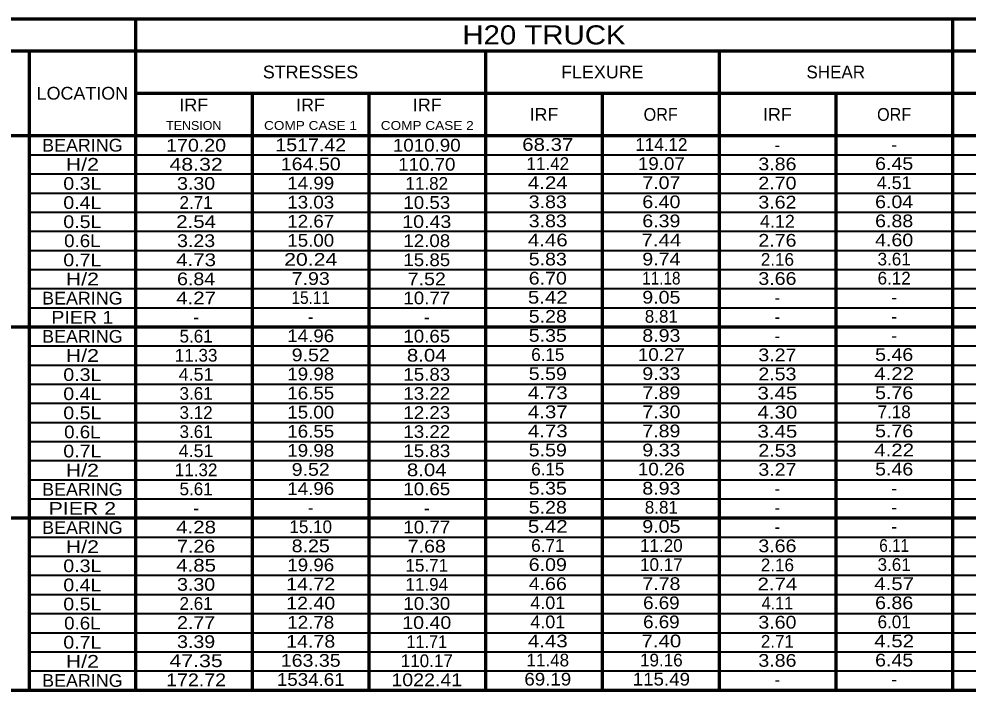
# Model space of a CAD drawing. Extents: x -1807 to -1668, y -81 to 6.
# Drawn here: x -1758.28 to -1713.57, y -25.85 to 5.78 of the extents above; entities that cross this region are included whole.
import ezdxf
from ezdxf.enums import TextEntityAlignment as Align

# ---------------------------------------------------------------- set-up
doc = ezdxf.new("R2010")
doc.units = 0
doc.header["$LTSCALE"] = 0.24
doc.layers.add('1', color=7, linetype='Continuous', lineweight=70)
doc.layers.add('5', color=7, linetype='Continuous', lineweight=40)
doc.layers.add('21', color=7, linetype='Continuous')
doc.layers.add('9', color=7, linetype='Continuous')

msp = doc.modelspace()

# ---------------------------------------------------------------- linework, layer by layer
at = {"layer": '1'}
for p, q in [((-1761.797, 5.7798), (-1675.797, 5.7798)), ((-1752.797, 5.7798), (-1752.797, -25.8503)), ((-1714.297, 5.7798), (-1714.297, -25.8503)), ((-1761.797, 4.2798), (-1675.797, 4.2798)), ((-1757.797, 4.2798), (-1757.797, -25.8503)), ((-1736.297, 4.2798), (-1736.297, -25.8503)), ((-1725.297, 4.2798), (-1725.297, -25.8503)), ((-1752.797, 2.2798), (-1675.797, 2.2798)), ((-1747.297, 2.2798), (-1747.297, -25.8503)), ((-1741.797, 2.2798), (-1741.797, -25.8503)), ((-1730.797, 2.2798), (-1730.797, -25.8503)), ((-1719.797, 2.2798), (-1719.797, -25.8503)), ((-1761.797, 0.2798), (-1675.797, 0.2798)), ((-1761.797, -8.7306), (-1675.797, -8.7306)), ((-1761.797, -17.741), (-1675.797, -17.741)), ((-1761.797, -25.8503), (-1675.797, -25.8503))]:
    msp.add_line(p, q, dxfattribs=at)
at = {"layer": '5'}
for p, q in [((-1757.797, -0.6212), (-1675.797, -0.6212)), ((-1757.797, -1.5222), (-1675.797, -1.5222)), ((-1757.797, -2.4232), (-1675.797, -2.4232)), ((-1757.797, -3.3243), (-1675.797, -3.3243)), ((-1757.797, -4.2253), (-1675.797, -4.2253)), ((-1757.797, -5.1264), (-1675.797, -5.1264)), ((-1757.797, -6.0274), (-1675.797, -6.0274)), ((-1757.797, -6.9285), (-1675.797, -6.9285)), ((-1757.797, -7.8295), (-1675.797, -7.8295)), ((-1757.797, -9.6316), (-1675.797, -9.6316)), ((-1757.797, -10.5327), (-1675.797, -10.5327)), ((-1757.797, -11.4337), (-1675.797, -11.4337)), ((-1757.797, -12.3347), (-1675.797, -12.3347)), ((-1757.797, -13.2357), (-1675.797, -13.2357)), ((-1757.797, -14.1368), (-1675.797, -14.1368)), ((-1757.797, -15.0378), (-1675.797, -15.0378)), ((-1757.797, -15.9389), (-1675.797, -15.9389)), ((-1757.797, -16.8399), (-1675.797, -16.8399)), ((-1757.797, -18.642), (-1675.797, -18.642)), ((-1757.797, -19.5431), (-1675.797, -19.5431)), ((-1757.797, -20.4441), (-1675.797, -20.4441)), ((-1757.797, -21.3452), (-1675.797, -21.3452)), ((-1757.797, -22.2462), (-1675.797, -22.2462)), ((-1757.797, -23.1472), (-1675.797, -23.1472)), ((-1757.797, -24.0482), (-1675.797, -24.0482)), ((-1757.797, -24.9493), (-1675.797, -24.9493))]:
    msp.add_line(p, q, dxfattribs=at)

# ---------------------------------------------------------------- texts
at = {"layer": '1'}
for s, width, p in [('BEARING', 1.05, (-1755.2967, -0.4707)), ('H/2', 1.25, (-1755.2969, -1.3717)), ('0.3L', 1.15, (-1755.2968, -2.2727)), ('0.4L', 1.15, (-1755.2968, -3.1738)), ('0.5L', 1.15, (-1755.2968, -4.0748)), ('0.6L', 1.1, (-1755.2969, -4.9758)), ('0.7L', 1.15, (-1755.2968, -5.8769)), ('H/2', 1.25, (-1755.2969, -6.7779)), ('BEARING', 1.05, (-1755.2967, -7.679)), ('PIER 1', 1.15, (-1755.2968, -8.58)), ('BEARING', 1.05, (-1755.2967, -9.4811)), ('H/2', 1.25, (-1755.2969, -10.3821)), ('0.3L', 1.15, (-1755.2968, -11.2832)), ('0.4L', 1.15, (-1755.2968, -12.1842)), ('0.5L', 1.15, (-1755.2968, -13.0853)), ('0.6L', 1.1, (-1755.2969, -13.9863)), ('0.7L', 1.15, (-1755.2968, -14.8873)), ('H/2', 1.25, (-1755.2969, -15.7883)), ('BEARING', 1.05, (-1755.2967, -16.6894)), ('PIER 2', 1.25, (-1755.2969, -17.5904)), ('BEARING', 1.05, (-1755.2967, -18.4915)), ('H/2', 1.25, (-1755.2969, -19.3925)), ('0.3L', 1.15, (-1755.2968, -20.2936)), ('0.4L', 1.15, (-1755.2968, -21.1946)), ('0.5L', 1.15, (-1755.2968, -22.0957)), ('0.6L', 1.1, (-1755.2969, -22.9967)), ('0.7L', 1.15, (-1755.2968, -23.8977)), ('H/2', 1.25, (-1755.2969, -24.7987)), ('BEARING', 1.05, (-1755.2967, -25.6998))]:
    msp.add_text(s, height=0.6, dxfattribs=dict(at, width=width)).set_placement(p, align=Align.CENTER)
at = {"layer": '21'}
for s, width, p in [('STRESSES', 1.05, (-1744.5468, 2.9798)), ('FLEXURE', 1.05, (-1730.7968, 2.9798)), ('LOCATION', 1.05, (-1755.2968, 1.9798)), ('IRF', 1.05, (-1750.0468, 1.4298)), ('IRF', 1.05, (-1744.5468, 1.4298)), ('IRF', 1.05, (-1739.0468, 1.4298)), ('IRF', 1.05, (-1733.5468, 0.9798)), ('ORF', 0.95, (-1728.0469, 0.9798)), ('IRF', 1.05, (-1722.5468, 0.9798)), ('ORF', 0.95, (-1717.0469, 0.9798))]:
    msp.add_text(s, height=0.6, dxfattribs=dict(at, width=width)).set_placement(p, align=Align.CENTER)
msp.add_text('SHEAR', height=0.6, dxfattribs=at).set_placement((-1719.7968, 2.9798), align=Align.CENTER)
at = {"layer": '9'}
for s, height, width, p in [('H20 TRUCK', 0.9, 1.15, (-1733.5467, 4.5798)), ('TENSION', 0.4167, 1.05, (-1750.0468, 0.5525)), ('COMP CASE 1', 0.4167, 1.15, (-1744.5469, 0.5525)), ('COMP CASE 2', 0.4167, 1.15, (-1739.0469, 0.5525)), ('170.20', 0.6, 1.15, (-1749.9378, -0.4705)), ('1517.42', 0.6, 1.15, (-1744.5366, -0.4538)), ('1010.90', 0.6, 1.1, (-1739.0686, -0.4705)), ('68.37', 0.6, 1.2, (-1733.3665, -0.4371)), ('48.32', 0.6, 1.25, (-1749.9378, -1.3705)), ('164.50', 0.6, 1.15, (-1744.5366, -1.3538)), ('110.70', 0.6, 1.1, (-1739.0686, -1.3705)), ('19.07', 0.6, 1.1, (-1728.0156, -1.3371)), ('3.86', 0.6, 1.15, (-1722.5476, -1.3538)), ('6.45', 0.6, 1.15, (-1717.046, -1.3371)), ('3.30', 0.6, 1.15, (-1749.9378, -2.2705)), ('14.99', 0.6, 1.1, (-1744.5366, -2.2538)), ('4.24', 0.6, 1.2, (-1733.3666, -2.2371)), ('7.07', 0.6, 1.15, (-1728.0155, -2.2371)), ('2.70', 0.6, 1.15, (-1722.5475, -2.2538)), ('4.51', 0.6, 1.05, (-1717.0461, -2.2371)), ('13.03', 0.6, 1.1, (-1744.5366, -3.1538)), ('10.53', 0.6, 1.1, (-1739.0686, -3.1705)), ('3.83', 0.6, 1.15, (-1733.3666, -3.1371)), ('6.40', 0.6, 1.15, (-1728.0156, -3.1371)), ('3.62', 0.6, 1.15, (-1722.5475, -3.1538)), ('6.04', 0.6, 1.15, (-1717.0461, -3.1371)), ('2.54', 0.6, 1.2, (-1749.9378, -4.0705)), ('12.67', 0.6, 1.1, (-1744.5366, -4.0538)), ('10.43', 0.6, 1.15, (-1739.0686, -4.0705)), ('3.83', 0.6, 1.15, (-1733.3666, -4.0371)), ('6.39', 0.6, 1.15, (-1728.0155, -4.0371)), ('4.12', 0.6, 1.05, (-1722.5475, -4.0538)), ('6.88', 0.6, 1.15, (-1717.046, -4.0371)), ('3.23', 0.6, 1.15, (-1749.9378, -4.9705)), ('15.00', 0.6, 1.1, (-1744.5366, -4.9538)), ('12.08', 0.6, 1.1, (-1739.0686, -4.9705)), ('4.46', 0.6, 1.2, (-1733.3666, -4.9371)), ('7.44', 0.6, 1.2, (-1728.0156, -4.9371)), ('2.76', 0.6, 1.15, (-1722.5476, -4.9538)), ('4.60', 0.6, 1.15, (-1717.0461, -4.9371)), ('4.73', 0.6, 1.2, (-1749.9378, -5.8705)), ('20.24', 0.6, 1.25, (-1744.5366, -5.8538)), ('15.85', 0.6, 1.1, (-1739.0686, -5.8705)), ('5.83', 0.6, 1.15, (-1733.3666, -5.8371)), ('9.74', 0.6, 1.15, (-1728.0155, -5.8371)), ('6.84', 0.6, 1.15, (-1749.9378, -6.7705)), ('7.93', 0.6, 1.15, (-1744.5366, -6.7538)), ('7.52', 0.6, 1.15, (-1739.0686, -6.7705)), ('6.70', 0.6, 1.15, (-1733.3666, -6.7371)), ('11.18', 0.6, 0.9, (-1728.0155, -6.7371)), ('3.66', 0.6, 1.15, (-1722.5475, -6.7538)), ('4.27', 0.6, 1.2, (-1749.9378, -7.6705)), ('15.11', 0.6, 0.9, (-1744.5366, -7.6538)), ('10.77', 0.6, 1.1, (-1739.0686, -7.6705)), ('5.42', 0.6, 1.2, (-1733.3666, -7.6371)), ('9.05', 0.6, 1.15, (-1728.0156, -7.6371)), ('5.28', 0.6, 1.15, (-1733.3666, -8.5371)), ('14.96', 0.6, 1.1, (-1744.5366, -9.4538)), ('10.65', 0.6, 1.1, (-1739.0686, -9.4705)), ('5.35', 0.6, 1.15, (-1733.3666, -9.4371)), ('8.93', 0.6, 1.15, (-1728.0155, -9.4371)), ('9.52', 0.6, 1.15, (-1744.5366, -10.3538)), ('8.04', 0.6, 1.2, (-1739.0686, -10.3705)), ('10.27', 0.6, 1.1, (-1728.0155, -10.3371)), ('3.27', 0.6, 1.15, (-1722.5476, -10.3538)), ('5.46', 0.6, 1.15, (-1717.0461, -10.3371)), ('4.51', 0.6, 1.05, (-1749.9378, -11.2705)), ('19.98', 0.6, 1.1, (-1744.5366, -11.2538)), ('15.83', 0.6, 1.1, (-1739.0686, -11.2705)), ('5.59', 0.6, 1.15, (-1733.3666, -11.2371)), ('9.33', 0.6, 1.15, (-1728.0155, -11.2371)), ('2.53', 0.6, 1.15, (-1722.5476, -11.2538)), ('4.22', 0.6, 1.2, (-1717.0461, -11.2371)), ('16.55', 0.6, 1.1, (-1744.5366, -12.1538)), ('13.22', 0.6, 1.1, (-1739.0686, -12.1705)), ('4.73', 0.6, 1.2, (-1733.3665, -12.1371)), ('7.89', 0.6, 1.15, (-1728.0156, -12.1371)), ('3.45', 0.6, 1.2, (-1722.5476, -12.1538)), ('5.76', 0.6, 1.15, (-1717.0461, -12.1371)), ('15.00', 0.6, 1.1, (-1744.5366, -13.0538)), ('12.23', 0.6, 1.1, (-1739.0686, -13.0705)), ('4.37', 0.6, 1.2, (-1733.3665, -13.0371)), ('7.30', 0.6, 1.15, (-1728.0155, -13.0371)), ('4.30', 0.6, 1.2, (-1722.5475, -13.0538)), ('16.55', 0.6, 1.1, (-1744.5366, -13.9538)), ('13.22', 0.6, 1.1, (-1739.0686, -13.9705)), ('4.73', 0.6, 1.2, (-1733.3665, -13.9371)), ('7.89', 0.6, 1.15, (-1728.0156, -13.9371)), ('3.45', 0.6, 1.2, (-1722.5476, -13.9538)), ('5.76', 0.6, 1.15, (-1717.0461, -13.9371)), ('4.51', 0.6, 1.05, (-1749.9378, -14.8705)), ('19.98', 0.6, 1.1, (-1744.5366, -14.8538)), ('15.83', 0.6, 1.1, (-1739.0686, -14.8705)), ('5.59', 0.6, 1.15, (-1733.3666, -14.8371)), ('9.33', 0.6, 1.15, (-1728.0155, -14.8371)), ('2.53', 0.6, 1.15, (-1722.5476, -14.8538)), ('4.22', 0.6, 1.2, (-1717.0461, -14.8371)), ('9.52', 0.6, 1.15, (-1744.5366, -15.7538)), ('8.04', 0.6, 1.2, (-1739.0686, -15.7705)), ('10.26', 0.6, 1.1, (-1728.0155, -15.7371)), ('3.27', 0.6, 1.15, (-1722.5476, -15.7538)), ('5.46', 0.6, 1.15, (-1717.0461, -15.7371)), ('14.96', 0.6, 1.1, (-1744.5366, -16.6538)), ('10.65', 0.6, 1.1, (-1739.0686, -16.6705)), ('5.35', 0.6, 1.15, (-1733.3666, -16.6371)), ('8.93', 0.6, 1.15, (-1728.0155, -16.6371)), ('5.28', 0.6, 1.15, (-1733.3666, -17.5371)), ('4.28', 0.6, 1.2, (-1749.9378, -18.4705)), ('10.77', 0.6, 1.1, (-1739.0686, -18.4705)), ('5.42', 0.6, 1.2, (-1733.3666, -18.4371)), ('9.05', 0.6, 1.15, (-1728.0156, -18.4371)), ('7.26', 0.6, 1.15, (-1749.9378, -19.3705)), ('8.25', 0.6, 1.15, (-1744.5367, -19.3538)), ('7.68', 0.6, 1.15, (-1739.0686, -19.3705)), ('3.66', 0.6, 1.15, (-1722.5475, -19.3538)), ('6.11', 0.6, 0.9, (-1717.0461, -19.3371)), ('4.85', 0.6, 1.2, (-1749.9378, -20.2705)), ('19.96', 0.6, 1.1, (-1744.5366, -20.2538)), ('6.09', 0.6, 1.15, (-1733.3665, -20.2371)), ('3.30', 0.6, 1.15, (-1749.9378, -21.1705)), ('14.72', 0.6, 1.15, (-1744.5366, -21.1538)), ('4.66', 0.6, 1.15, (-1733.3665, -21.1371)), ('7.78', 0.6, 1.15, (-1728.0156, -21.1371)), ('2.74', 0.6, 1.2, (-1722.5476, -21.1538)), ('4.57', 0.6, 1.2, (-1717.0461, -21.1371)), ('12.40', 0.6, 1.15, (-1744.5366, -22.0538)), ('10.30', 0.6, 1.1, (-1739.0686, -22.0705)), ('4.01', 0.6, 1.05, (-1733.3665, -22.0371)), ('6.69', 0.6, 1.1, (-1728.0155, -22.0371)), ('4.11', 0.6, 0.95, (-1722.5475, -22.0538)), ('6.86', 0.6, 1.15, (-1717.046, -22.0371)), ('12.78', 0.6, 1.1, (-1744.5366, -22.9538)), ('4.01', 0.6, 1.05, (-1733.3665, -22.9371)), ('6.69', 0.6, 1.1, (-1728.0155, -22.9371)), ('3.60', 0.6, 1.15, (-1722.5476, -22.9538)), ('2.77', 0.6, 1.15, (-1749.9378, -22.9705)), ('10.40', 0.6, 1.15, (-1739.0686, -22.9705)), ('14.78', 0.6, 1.15, (-1744.5366, -23.8538)), ('4.43', 0.6, 1.2, (-1733.3666, -23.8371)), ('7.40', 0.6, 1.2, (-1728.0155, -23.8371)), ('4.52', 0.6, 1.2, (-1717.0461, -23.8371)), ('3.39', 0.6, 1.15, (-1749.9378, -23.8705)), ('11.71', 0.6, 0.95, (-1739.0687, -23.8705)), ('163.35', 0.6, 1.15, (-1744.5366, -24.7538)), ('3.86', 0.6, 1.15, (-1722.5476, -24.7538)), ('6.45', 0.6, 1.15, (-1717.046, -24.7371)), ('47.35', 0.6, 1.25, (-1749.9378, -24.7705)), ('69.19', 0.6, 1.1, (-1733.3665, -25.6371)), ('115.49', 0.6, 1.1, (-1728.0155, -25.6371)), ('172.72', 0.6, 1.15, (-1749.9378, -25.6705)), ('1534.61', 0.6, 1.1, (-1744.5366, -25.6538)), ('1022.41', 0.6, 1.15, (-1739.0686, -25.6705))]:
    msp.add_text(s, height=height, dxfattribs=dict(at, width=width)).set_placement(p, align=Align.CENTER)
for s, p in [('114.12', (-1728.0155, -0.4371)), ('-', (-1722.5475, -0.4538)), ('-', (-1717.0461, -0.4371)), ('11.42', (-1733.3665, -1.3371)), ('11.82', (-1739.0686, -2.2705)), ('2.71', (-1749.9378, -3.1705)), ('2.16', (-1722.5475, -5.8538)), ('3.61', (-1717.046, -5.8371)), ('6.12', (-1717.046, -6.7371)), ('-', (-1722.5475, -7.6538)), ('-', (-1717.0461, -7.6371)), ('8.81', (-1728.0156, -8.5371)), ('-', (-1749.9378, -8.5705)), ('-', (-1744.5366, -8.5538)), ('-', (-1739.0686, -8.5705)), ('-', (-1722.5475, -8.5538)), ('-', (-1717.0461, -8.5371)), ('5.61', (-1749.9378, -9.4705)), ('-', (-1722.5475, -9.4538)), ('-', (-1717.0461, -9.4371)), ('11.33', (-1749.9378, -10.3705)), ('6.15', (-1733.3665, -10.3371)), ('3.61', (-1749.9378, -12.1705)), ('3.12', (-1749.9378, -13.0705)), ('7.18', (-1717.0461, -13.0371)), ('3.61', (-1749.9378, -13.9705)), ('11.32', (-1749.9378, -15.7705)), ('6.15', (-1733.3665, -15.7371)), ('5.61', (-1749.9378, -16.6705)), ('-', (-1722.5475, -16.6538)), ('-', (-1717.0461, -16.6371)), ('8.81', (-1728.0156, -17.5371)), ('-', (-1749.9378, -17.5705)), ('-', (-1744.5366, -17.5538)), ('-', (-1739.0686, -17.5705)), ('-', (-1722.5475, -17.5538)), ('-', (-1717.0461, -17.5371)), ('15.10', (-1744.5367, -18.4538)), ('-', (-1722.5475, -18.4538)), ('-', (-1717.0461, -18.4371)), ('6.71', (-1733.3665, -19.3371)), ('11.20', (-1728.0156, -19.3371)), ('15.71', (-1739.0686, -20.2705)), ('10.17', (-1728.0156, -20.2371)), ('2.16', (-1722.5475, -20.2538)), ('3.61', (-1717.046, -20.2371)), ('11.94', (-1739.0686, -21.1705)), ('2.61', (-1749.9378, -22.0705)), ('6.01', (-1717.0461, -22.9371)), ('2.71', (-1722.5475, -23.8538)), ('11.48', (-1733.3665, -24.7371)), ('19.16', (-1728.0156, -24.7371)), ('110.17', (-1739.0686, -24.7705)), ('-', (-1722.5475, -25.6538)), ('-', (-1717.0461, -25.6371))]:
    msp.add_text(s, height=0.6, dxfattribs=at).set_placement(p, align=Align.CENTER)

doc.saveas('drawing.dxf')
